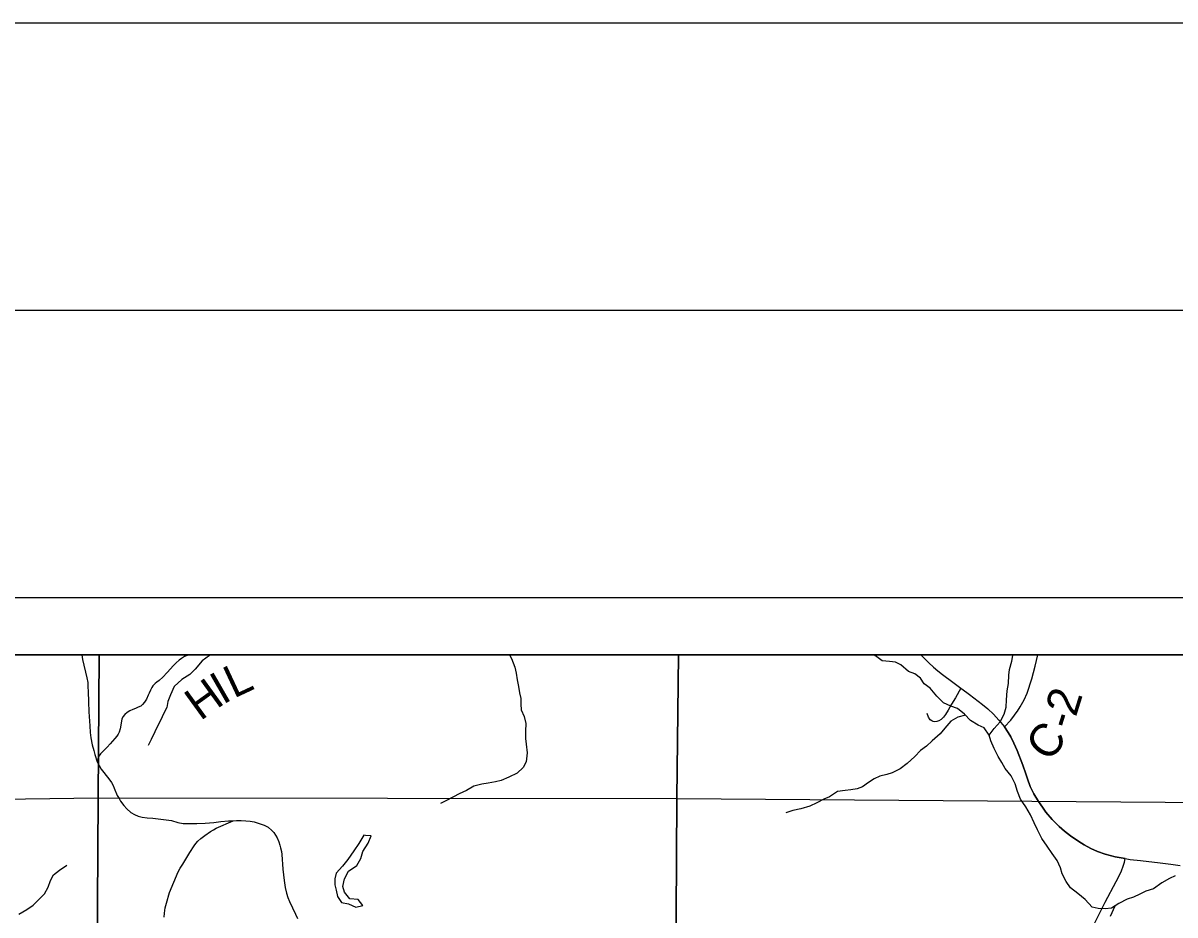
# Model space of a CAD drawing. Extents: x 0 to 34, y 0 to 22.
# Drawn here: x 5.667 to 7.673, y 20.447 to 22 of the extents above; entities that cross this region are included whole.
import ezdxf

# ---------------------------------------------------------------- set-up
doc = ezdxf.new("R2010")
doc.units = 0
for name, color, linetype in [('Default', 7, 'Continuous'), ('GM_X_County_Road', 7, 'Continuous'), ('GM_X_County_Road_Text', 7, 'Continuous'), ('GM_X_Minor_Lake', 7, 'Continuous'), ('GM_X_Minor_River', 7, 'Continuous'), ('GM_X_Rail_Line', 7, 'Continuous'), ('GM_X_Section', 7, 'Continuous'), ('GM_X_State_Route', 7, 'Continuous'), ('GM_X_Township_Road', 7, 'Continuous'), ('GM_X_Township_Road_Text', 7, 'Continuous'), ('SH_Border', 7, 'Continuous'), ('SH_Cut_Line', 7, 'Continuous'), ('SH_Data', 7, 'Continuous')]:
    doc.layers.add(name, color=color, linetype=linetype)

msp = doc.modelspace()

# ---------------------------------------------------------------- linework, layer by layer
at = {"layer": 'Default'}
for points in [[(5.7998, 20.9), (4.5799, 20.9), (4.5766, 20.6934), (4.5761, 20.6339), (5.7984, 20.651)], [(6.8087, 20.9), (5.7998, 20.9), (5.7984, 20.651), (6.806, 20.65)], [(7.8121, 20.9), (6.8087, 20.9), (6.806, 20.65), (7.8107, 20.6421)]]:
    msp.add_lwpolyline(points, close=True, dxfattribs=at)
at = {"layer": 'GM_X_County_Road'}
for points in [[(7.3954, 20.7966), (7.3992, 20.802), (7.404, 20.8096), (7.411, 20.8213), (7.4161, 20.833), (7.4244, 20.8583), (7.4302, 20.8803), (7.4323, 20.8899), (7.4344, 20.9)], [(7.3769, 20.7744), (7.3878, 20.7862), (7.3942, 20.7948), (7.3954, 20.7966)], [(7.4136, 20.6925), (7.4084, 20.7079), (7.3989, 20.7333), (7.3931, 20.7459), (7.3874, 20.7571), (7.3829, 20.7647), (7.3769, 20.7744)], [(7.5868, 20.5452), (7.5693, 20.5484), (7.5519, 20.5531), (7.5385, 20.5577), (7.5272, 20.5626), (7.5156, 20.5688), (7.506, 20.5748), (7.4917, 20.5845), (7.4809, 20.593), (7.4717, 20.601), (7.4598, 20.6131), (7.4488, 20.626), (7.4425, 20.6346), (7.4357, 20.6444), (7.4279, 20.6576), (7.4215, 20.6705), (7.4165, 20.6838), (7.4136, 20.6925)], [(7.5314, 20.4288), (7.5522, 20.4695), (7.5712, 20.5052), (7.5797, 20.5223), (7.5838, 20.5334), (7.5853, 20.5386), (7.5868, 20.5452)]]:
    msp.add_lwpolyline(points, dxfattribs=at)
at = {"layer": 'GM_X_Minor_Lake'}
for points in [[(6.264, 20.5856), (6.2608, 20.5857), (6.2521, 20.5713), (6.2438, 20.5587), (6.2329, 20.5435), (6.2238, 20.5317), (6.2125, 20.5195), (6.2102, 20.5096), (6.2107, 20.4994), (6.2126, 20.4899), (6.2149, 20.4789), (6.2218, 20.4687), (6.2344, 20.4661), (6.2473, 20.4604), (6.2594, 20.4635)], [(6.2594, 20.4635), (6.251, 20.4741), (6.2366, 20.4752), (6.2271, 20.4865), (6.2244, 20.4964), (6.227, 20.5097), (6.2341, 20.523), (6.2485, 20.5333), (6.256, 20.5451), (6.259, 20.5576), (6.2684, 20.5717), (6.2737, 20.585), (6.264, 20.5856)]]:
    msp.add_lwpolyline(points, dxfattribs=at)
at = {"layer": 'GM_X_Minor_River'}
for points in [[(5.9939, 20.9), (5.9924, 20.8987), (5.9796, 20.8896), (5.9675, 20.8747), (5.9577, 20.8656), (5.944, 20.8572), (5.9308, 20.8446), (5.924, 20.8305), (5.9195, 20.8184), (5.918, 20.8081), (5.9128, 20.7982), (5.9071, 20.7857), (5.9018, 20.7758), (5.897, 20.7659), (5.8909, 20.7522), (5.8853, 20.7423)], [(6.5146, 20.9), (6.518, 20.8938), (6.5238, 20.8783), (6.5261, 20.8681), (6.5281, 20.8563), (6.5304, 20.8446), (6.532, 20.834), (6.5343, 20.8241), (6.5343, 20.8139), (6.5351, 20.8044), (6.5401, 20.7926), (6.5432, 20.7805), (6.5425, 20.7668), (6.5426, 20.7543), (6.5438, 20.7445), (6.5454, 20.7293), (6.5439, 20.7133), (6.5382, 20.7038), (6.528, 20.6939), (6.5133, 20.6866), (6.5, 20.6809), (6.4901, 20.6786), (6.4776, 20.6766), (6.4666, 20.6747), (6.4526, 20.6712), (6.4397, 20.6639), (6.4272, 20.6578), (6.4173, 20.6528), (6.4037, 20.6456), (6.3942, 20.6413)], [(7.3775, 20.7022), (7.3721, 20.7124), (7.3653, 20.723), (7.3588, 20.7367), (7.353, 20.7503), (7.3499, 20.7602), (7.3411, 20.7726), (7.3309, 20.7772), (7.3175, 20.7858), (7.3068, 20.7968), (7.2946, 20.8062), (7.2829, 20.8107), (7.2703, 20.8164), (7.2589, 20.8281), (7.247, 20.8421), (7.2367, 20.8492), (7.2306, 20.8591), (7.2203, 20.867), (7.2093, 20.8711), (7.1963, 20.8824), (7.1868, 20.8869), (7.1762, 20.8884), (7.1633, 20.8895), (7.1518, 20.8982), (7.1507, 20.9)], [(7.35, 20.7598), (7.3586, 20.7716), (7.3688, 20.7834), (7.3763, 20.7967), (7.3797, 20.8089), (7.38, 20.8214), (7.3811, 20.8373), (7.3837, 20.8502), (7.384, 20.8647), (7.3851, 20.8742), (7.3892, 20.8886), (7.3911, 20.8985), (7.3913, 20.9)], [(7.3086, 20.795), (7.2951, 20.7914), (7.283, 20.7842), (7.2728, 20.772), (7.2648, 20.7621), (7.2508, 20.7499), (7.241, 20.7407), (7.2304, 20.7331), (7.2202, 20.7228), (7.2073, 20.7106), (7.1949, 20.7014), (7.1812, 20.6945), (7.1717, 20.6914), (7.1596, 20.6884), (7.1497, 20.6841), (7.1395, 20.6776), (7.1293, 20.67), (7.1198, 20.6665), (7.1092, 20.665), (7.0993, 20.6634), (7.086, 20.6622), (7.0716, 20.6527), (7.0622, 20.6485), (7.05, 20.6423), (7.0375, 20.6362), (7.022, 20.632), (7.0083, 20.6289), (6.9958, 20.625)], [(7.6738, 20.5153), (7.6639, 20.5103), (7.6507, 20.5027), (7.6359, 20.4923), (7.6226, 20.4881), (7.612, 20.4831), (7.6014, 20.4778), (7.59, 20.4747), (7.5756, 20.467), (7.5631, 20.4586), (7.5521, 20.4574), (7.5396, 20.4582), (7.5293, 20.4604), (7.5168, 20.4736), (7.5042, 20.4842), (7.4916, 20.494), (7.484, 20.505), (7.4771, 20.5186), (7.474, 20.5292), (7.4686, 20.5417), (7.4598, 20.5538), (7.451, 20.5667), (7.4415, 20.5799), (7.4338, 20.5951), (7.4281, 20.6072), (7.4219, 20.6212), (7.4139, 20.6352), (7.4047, 20.6485), (7.399, 20.6617), (7.3951, 20.675), (7.3882, 20.689), (7.3775, 20.7022)], [(5.7048, 20.4838), (5.7111, 20.4956), (5.7152, 20.5071), (5.7205, 20.5166), (5.7307, 20.525), (5.7439, 20.5338)], [(5.6602, 20.4483), (5.6742, 20.4563), (5.6851, 20.464), (5.6942, 20.4735), (5.7048, 20.4838)], [(7.5687, 20.4624), (7.5609, 20.4442)]]:
    msp.add_lwpolyline(points, dxfattribs=at)
at = {"layer": 'GM_X_Rail_Line'}
msp.add_lwpolyline([(5.4171, 18.6266), (7.3845, 18.6186), (7.3876, 18.6186), (7.7217, 18.6188), (7.7247, 18.6188), (7.7665, 18.6188), (7.7949, 18.6196), (7.7955, 18.662), (7.7955, 18.6643), (7.8036, 19.6113), (7.8037, 19.6169), (7.8038, 19.6317), (8.8143, 19.6303), (8.8149, 19.7665), (8.8193, 20.9), (4.5874, 20.9)], dxfattribs=at)
at = {"layer": 'GM_X_Section'}
for points in [[(4.5761, 20.6339), (5.7984, 20.651), (5.7918, 19.6342), (4.5644, 19.6379), (4.5646, 19.6808)], [(6.806, 20.65), (6.8002, 19.6351), (5.7918, 19.6342), (5.7984, 20.651)], [(6.806, 20.65), (7.8107, 20.6421), (7.8055, 19.6329), (6.8002, 19.6351)]]:
    msp.add_lwpolyline(points, close=True, dxfattribs=at)
at = {"layer": 'GM_X_State_Route'}
for points in [[(7.2307, 20.9), (7.2373, 20.8935), (7.2449, 20.8861), (7.253, 20.8787), (7.2607, 20.8718), (7.2687, 20.8654), (7.2864, 20.8523), (7.3008, 20.8421), (7.3111, 20.8343), (7.3155, 20.8309)], [(7.3155, 20.8309), (7.3383, 20.8136), (7.3475, 20.8059), (7.3576, 20.7965), (7.3669, 20.7863), (7.3769, 20.7744)], [(7.3769, 20.7744), (7.3829, 20.7647), (7.3874, 20.7571), (7.3931, 20.7459), (7.3989, 20.7333), (7.4084, 20.7079), (7.4136, 20.6925)], [(7.4136, 20.6925), (7.4165, 20.6838), (7.4215, 20.6705), (7.4279, 20.6576), (7.4357, 20.6444), (7.4425, 20.6346), (7.4488, 20.626), (7.4598, 20.6131), (7.4717, 20.601), (7.4809, 20.593), (7.4917, 20.5845), (7.506, 20.5748), (7.5156, 20.5688), (7.5272, 20.5626), (7.5385, 20.5577), (7.5519, 20.5531), (7.5693, 20.5484), (7.5868, 20.5452)], [(7.5868, 20.5452), (7.5953, 20.5437), (7.6136, 20.5416), (7.6478, 20.5377), (7.666, 20.5356), (7.6827, 20.5331)]]:
    msp.add_lwpolyline(points, dxfattribs=at)
at = {"layer": 'GM_X_Township_Road'}
for points in [[(5.7699, 20.9), (5.7709, 20.8917), (5.7787, 20.86), (5.7803, 20.8516), (5.7806, 20.8442), (5.7811, 20.8363), (5.7815, 20.8179), (5.7823, 20.8009), (5.7837, 20.7765), (5.7845, 20.7646), (5.7856, 20.7553), (5.7878, 20.7431), (5.7907, 20.7332), (5.7926, 20.7262), (5.7967, 20.7133)], [(5.9577, 20.9), (5.9548, 20.8991), (5.9485, 20.8968), (5.9437, 20.8937), (5.9391, 20.8904), (5.9342, 20.8861), (5.9296, 20.8811), (5.9184, 20.869), (5.9109, 20.8613), (5.9043, 20.8553), (5.9006, 20.8525), (5.8976, 20.8501), (5.8938, 20.846), (5.8918, 20.8429), (5.8893, 20.8385), (5.887, 20.8332), (5.8855, 20.8295), (5.8825, 20.8229), (5.8792, 20.8172), (5.8758, 20.8132), (5.8726, 20.8106), (5.8682, 20.8085), (5.8633, 20.8066), (5.8587, 20.8048), (5.8536, 20.8023), (5.8489, 20.7995), (5.8448, 20.7959), (5.8415, 20.7917), (5.8394, 20.788), (5.8366, 20.7708), (5.835, 20.7652), (5.8331, 20.7616), (5.8311, 20.7584), (5.8276, 20.754), (5.8193, 20.7447), (5.8138, 20.7392), (5.8053, 20.7307), (5.8022, 20.7275), (5.7995, 20.7237), (5.7978, 20.7191), (5.7967, 20.7133)], [(7.3008, 20.8421), (7.2914, 20.8249), (7.2844, 20.8139), (7.2784, 20.8034), (7.2739, 20.796), (7.2703, 20.7912), (7.2663, 20.7874), (7.2625, 20.785), (7.2586, 20.7837), (7.2548, 20.7833), (7.2522, 20.7838), (7.2502, 20.7848), (7.2473, 20.787), (7.2445, 20.7915), (7.2417, 20.7977)], [(5.7967, 20.7133), (5.8033, 20.7011), (5.8168, 20.6838), (5.8213, 20.6776), (5.8243, 20.6725), (5.8262, 20.6675), (5.8316, 20.6551), (5.8346, 20.6496), (5.8373, 20.6452), (5.8428, 20.6375), (5.8483, 20.6317), (5.8554, 20.6253), (5.8616, 20.6217), (5.8681, 20.6191), (5.8751, 20.6171), (5.8837, 20.6162), (5.8934, 20.6153), (5.9263, 20.6112), (5.9369, 20.6082), (5.9466, 20.6065), (5.97, 20.6061), (5.9847, 20.607), (6, 20.608), (6.0122, 20.6096), (6.0252, 20.611), (6.0333, 20.611), (6.0395, 20.6115), (6.0475, 20.6117), (6.0556, 20.611), (6.0628, 20.6103), (6.0698, 20.6089), (6.0788, 20.6064), (6.0874, 20.6032), (6.0944, 20.5999), (6.1009, 20.5943), (6.1043, 20.5904), (6.1072, 20.5861), (6.11, 20.5814), (6.113, 20.5742), (6.1149, 20.5683), (6.1161, 20.5638), (6.1175, 20.5577), (6.1181, 20.5521), (6.12, 20.5266), (6.1223, 20.507), (6.124, 20.495), (6.1264, 20.4851), (6.1287, 20.4776), (6.1316, 20.4704), (6.1418, 20.4483), (6.1456, 20.4406)], [(5.9131, 20.4429), (5.9138, 20.4498), (5.9151, 20.4592), (5.9171, 20.4673), (5.9228, 20.4863), (5.9377, 20.5219), (5.9413, 20.5284), (5.9456, 20.5354), (5.9581, 20.5555), (5.9655, 20.5673), (5.9684, 20.5713), (5.9718, 20.5752), (5.9769, 20.5803), (5.9838, 20.5854), (5.9941, 20.5922), (5.9989, 20.5953), (6.0036, 20.5979), (6.0333, 20.611)]]:
    msp.add_lwpolyline(points, dxfattribs=at)
at = {"layer": 'SH_Border'}
msp.add_lwpolyline([(1.5, 21.5), (33.5, 21.5), (33.5, 0.5), (1.5, 0.5)], close=True, dxfattribs=at)
at = {"layer": 'SH_Cut_Line'}
msp.add_lwpolyline([(0, 0), (34, 0), (34, 22), (0, 22)], close=True, dxfattribs=at)
msp.add_lwpolyline([(8.9, 14.624), (8.9, 20.9), (2.1, 20.9), (2.1, 14.1)], dxfattribs=at)
at = {"layer": 'SH_Data'}
for p, q in [((2, 21), (9, 21)), ((2.1, 20.9), (8.9, 20.9))]:
    msp.add_line(p, q, dxfattribs=at)

# ---------------------------------------------------------------- texts
at = {"layer": 'GM_X_County_Road_Text'}
for s, rotation, p in [('2', 72.7021, (7.5008, 20.7904)), ('-', 72.4772, (7.4937, 20.7679)), ('C', 51.2579, (7.4537, 20.7114))]:
    msp.add_text(s, height=0.0568, rotation=rotation, dxfattribs=at).set_placement(p)
at = {"layer": 'GM_X_Township_Road_Text'}
for s, rotation, p in [('I', 29.862, (6.0154, 20.8125)), ('L', 25.0508, (6.0345, 20.8235)), ('H', 35.9052, (5.9763, 20.784))]:
    msp.add_text(s, height=0.0568, rotation=rotation, dxfattribs=at).set_placement(p)

doc.saveas('drawing.dxf')
